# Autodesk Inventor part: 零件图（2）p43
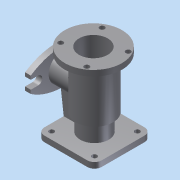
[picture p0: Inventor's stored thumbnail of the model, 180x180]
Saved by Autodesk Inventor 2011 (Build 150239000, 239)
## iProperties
Created: 2014-01
Part Number: 零件图（2）p43
Document SubType Name: Modeling
Designer: Administrator
Density: 1 g/cm^3
Author: Administrator
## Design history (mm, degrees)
sketch "草图1"
  geometry: L1 (-40, 40)-(40, 40); L2 (40, 40)-(40, -40); L3 (40, -40)-(-40, -40); L4 (-40, -40)-(-40, 40); 3 further points
  constraints: 8 end point, 2 midpoint, 2 parallel, 1 horizontal, 1 horizontal alignment, 1 perpendicular, 1 vertical alignment
  dimensions: "d0" = 80 distance of L1.start L1.end; "d1" = 80 distance of L3.end L1.start
extrude "拉伸1" new body sketch "草图1" distance "d2" = 8; taper "d3" = 0 deg
fillet "圆角1" dims "d4" = 10
fillet "圆角2" dims "d5" = 10
fillet "圆角3" dims "d6" = 10
fillet "圆角4" dims "d7" = 10
hole "Hole1" diameter "d10" = 7; stored, may be unused: countersink angle "d14" = 90 deg, drill point angle "d16" = 118 deg; dims "d8" = 10, "d9" = 10, "d11" = 6, "d12" = 4, "d13" = 2, "d15" = 8
mirror "镜像1"
mirror "镜像2"
sketch "草图2"
  geometry: C1 r 20 at (0, 0); 1 further point
  constraints: 1 centre point, 1 coincident
  dimensions: "d17" = 40 diameter of C1
extrude "拉伸2" join sketch "草图2" distance "d18" = 32; taper "d19" = 0 deg
node "工作平面1"
node "工作平面2"
sketch "草图4"
  geometry: C1 r 40 at (-1.476, 0); 1 further point
  constraints: 1 centre point
  dimensions: "d34" = 80 diameter of C1
extrude "拉伸4" join sketch "草图4" distance "d35" = 8; taper "d36" = 0 deg
sketch "草图5" dims "d46" = 66
  geometry: C1 r 40 at (0, 0) reference; C2 r 3.5 at (-27.495, -18.25); 2 further points
  constraints: 1 centre point, 1 coincident, 3 other
  dimensions: "d47" = 7 diameter of C2
hole "Hole4" sketch "草图5" at (-27.495, -18.25) diameter "d48" = 7; stored, may be unused: countersink angle "d52" = 90 deg, drill point angle "d54" = 0 deg; dims "d49" = 6, "d50" = 4, "d51" = 2, "d53" = 8
pattern_circular "环形阵列1" dims angle "d56" = 360 deg
node "工作平面3"
sketch "草图7"
  geometry: C1 r 26 at (0, 0); 1 further point
  constraints: 1 centre point, 1 coincident
  dimensions: "d62" = 52 diameter of C1
extrude "拉伸6" join sketch "草图7" distance "d63" = 70; taper "d64" = 0 deg
hole "Hole6" diameter "d76" = 40; stored, may be unused: countersink angle "d80" = 90 deg, drill point angle "d82" = 0 deg; dims "d74" = 10, "d75" = 10, "d77" = 6, "d78" = 4, "d79" = 2, "d81" = 70
hole "Hole7" diameter "d85" = 28; stored, may be unused: countersink angle "d89" = 90 deg, drill point angle "d91" = 118 deg; dims "d83" = 10, "d84" = 10, "d86" = 6, "d87" = 4, "d88" = 2, "d90" = 70
node "工作平面4"
sketch "草图8"
  geometry: L1 (26, 102)-(-26, 102) reference; L2 (-26, 32)-(26, 32) reference; L3 (26, 32)-(26, 102) reference; L4 (-26, 32)-(-26, 102) reference; L5 (-30, 0)-(30, 0) reference; C1 r 20 at (0, 65); 1 further point
  constraints: 1 centre point
  dimensions: "d93" = 40 diameter of C1; "d94" = 65 distance of point (0, 0) C1.centre
extrude "拉伸7" join sketch "草图8" stored distance "d95" = 62; taper "d96" = 0 deg
hole "Hole8" diameter "d99" = 28; stored, may be unused: countersink angle "d103" = 90 deg, drill point angle "d105" = 0 deg; dims "d97" = 10, "d98" = 10, "d100" = 6, "d101" = 4, "d102" = 2, "d104" = 52
sketch "草图9"
  geometry: L1 (45, 76.144)-(45, -7.071); L2 (-45, 76.144)-(-45, 53.856); C1 r 20 at (0, 65) reference; C2 r 14 at (0, 65) reference; A1 r 80 centre (0, 120) between (-45, 53.856) and (45, 53.856); A2 r 80 centre (0, 10) between (45, 76.144) and (-45, 76.144); A3 r 80 centre (0, 10) between (-45, -56.144) and (45, -56.144); 1 further point
  constraints: 6 point on circle, 4 end point, 3 centre point, 3 point on line
  dimensions: "d109" = 45 distance from line of C1.centre L1; "d110" = 160 diameter of A1; "d111" = 55 distance of A2.centre C1.centre; "d114" = 45 distance from line of L2 C1.centre
extrude "拉伸8" join sketch "草图9" distance "d115" = 8; taper "d116" = 0 deg
sketch "草图10"
  geometry: L1 (76.144, -45)-(53.856, -45) reference; L2 (53.856, 45)-(76.144, 45) reference; L3 (71, 35)-(71, 45); L4 (59, 35)-(59, 45); L5 (76.144, 45)-(53.856, 45) reference; C1 r 14 at (65, 0) reference; A1 r 80 centre (10, 0) between (76.144, -45) and (76.144, 45) reference; A2 r 80 centre (120, 0) between (53.856, 45) and (53.856, -45) reference; A3 r 6 centre (65, 35) between (59, 35) and (71, 35); 1 further point
  constraints: 4 end point, 2 point on circle, 2 point on line, 2 tangent, 1 centre point, 1 parallel, 1 perpendicular
  dimensions: "d117" = 12 diameter of A3; "d118" = 35 distance of A3.centre C1.centre
extrude "拉伸9" cut sketch "草图10" distance "d119" = 8; taper "d120" = 0 deg
mirror "镜像3"
sketch "草图11"
  geometry: L1 (44, 40)-(40, 8); 1 further point
  constraints: 2 end point
feature "加强筋1" sketch "草图11" dims "d121" = 1, "d122" = 6, "d123" = 0
node "实体1"
node "投影回路1"
other parameters: "d29" = 57, "d33" = 102, "d61" = 32, "d92" = -52
